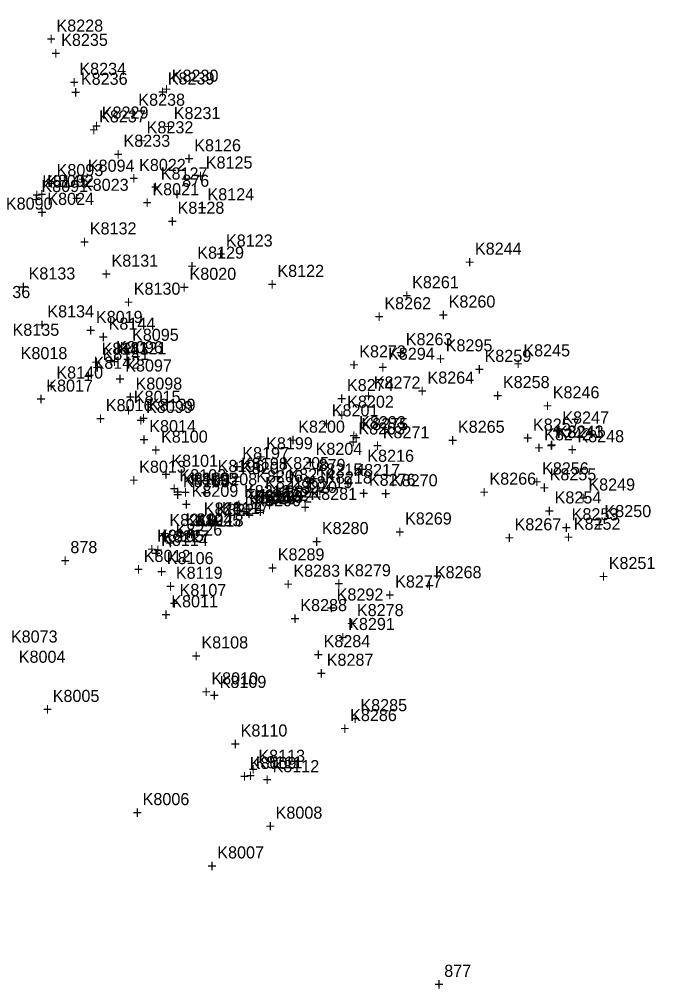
# Model space of a CAD drawing. Extents: x 1036751 to 1042192, y 772604 to 785439.
# Drawn here: x 1041667.1 to 1041798.6, y 774531.3 to 774731.8 of the extents above; entities that cross this region are included whole.
import ezdxf

# ---------------------------------------------------------------- set-up
doc = ezdxf.new("R2010")
doc.units = 0
for name, color, linetype in [('S_Buildings', 7, 'Continuous'), ('S_Buildings_SillElevation', 7, 'Continuous'), ('S_Control_Temp_Traverse', 7, 'Continuous'), ('S_Drainage_Culvert_Top', 7, 'Continuous'), ('S_Drainage_Invert', 7, 'Continuous'), ('S_Drainage_Waterway', 7, 'Continuous'), ('S_Ground_Elevation', 7, 'Continuous'), ('S_Ground_LevelString', 7, 'Continuous'), ('S_Ground_SpotElevation', 7, 'Continuous'), ('S_Roadway_Drive_Gravel', 7, 'Continuous'), ('S_Traffic_Post_Conc', 7, 'Continuous'), ('S_Trees_Decid_NonPay', 7, 'Continuous'), ('S_Trees_Decid_Pay', 7, 'Continuous'), ('S_Trees_TreeLine', 7, 'Continuous'), ('S_Utilities_GuyWire3', 7, 'Continuous'), ('S_Utilities_Pole_Power', 7, 'Continuous')]:
    doc.layers.add(name, color=color, linetype=linetype)

msp = doc.modelspace()

# ---------------------------------------------------------------- texts
at = {"layer": 'S_Buildings'}
for s, p in [('K8228', (1041674.79, 774729.22)), ('+', (1041672.73, 774726.47)), ('K8230', (1041698.64, 774718.86)), ('+', (1041696.57, 774716.11)), ('K8229', (1041684.16, 774711.23)), ('+', (1041682.1, 774708.48)), ('K8145', (1041671.84, 774696.97)), ('+', (1041669.77, 774694.22)), ('K8122', (1041720.5, 774678.48)), ('+', (1041718.44, 774675.73)), ('K8121', (1041687.87, 774662.5)), ('+', (1041685.81, 774659.75)), ('K8120', (1041700.97, 774635.52)), ('+', (1041698.91, 774632.77)), ('K8115', (1041714.71, 774631.45)), ('+', (1041712.65, 774628.7)), ('K8114', (1041696.46, 774622.84)), ('+', (1041694.4, 774620.09)), ('K8113', (1041716.57, 774578.16)), ('+', (1041714.51, 774575.41))]:
    msp.add_text(s, height=2.5, dxfattribs=at).set_placement(p)
at = {"layer": 'S_Buildings_SillElevation'}
for s, p in [('K8234', (1041679.53, 774720.28)), ('+', (1041677.47, 774717.53)), ('K8139', (1041693.9, 774650.78)), ('+', (1041691.84, 774648.03)), ('K8119', (1041699.5, 774616.03)), ('+', (1041697.43, 774613.28))]:
    msp.add_text(s, height=2.5, dxfattribs=at).set_placement(p)
at = {"layer": 'S_Control_Temp_Traverse'}
for s, p in [('876', (1041700.82, 774697.14)), ('876', (1041700.82, 774697.14)), ('+', (1041698.76, 774694.39)), ('+', (1041698.76, 774694.39)), ('879', (1041729.04, 774638.33)), ('+', (1041726.98, 774635.58)), ('878', (1041677.67, 774621.34)), ('878', (1041677.67, 774621.34)), ('878', (1041677.67, 774621.34)), ('+', (1041675.61, 774618.59)), ('+', (1041675.61, 774618.59)), ('+', (1041675.61, 774618.59)), ('877', (1041755.03, 774533.69)), ('877', (1041755.03, 774533.69)), ('877', (1041755.03, 774533.69)), ('877', (1041755.03, 774533.69)), ('+', (1041752.97, 774530.94)), ('+', (1041752.97, 774530.94)), ('+', (1041752.97, 774530.94)), ('+', (1041752.97, 774530.94))]:
    msp.add_text(s, height=2.5, dxfattribs=at).set_placement(p)
at = {"layer": 'S_Drainage_Culvert_Top'}
for s, p in [('K8242', (1041775.71, 774644.67)), ('K8241', (1041778.24, 774645.13)), ('+', (1041773.65, 774641.92)), ('+', (1041776.18, 774642.38))]:
    msp.add_text(s, height=2.5, dxfattribs=at).set_placement(p)
at = {"layer": 'S_Drainage_Invert'}
for s, p in [('K8243', (1041778.35, 774645.24)), ('+', (1041776.29, 774642.49))]:
    msp.add_text(s, height=2.5, dxfattribs=at).set_placement(p)
at = {"layer": 'S_Drainage_Waterway'}
for s, p in [('K8244', (1041761.38, 774683.08)), ('+', (1041759.32, 774680.33)), ('K8245', (1041771.4, 774662.04)), ('+', (1041769.34, 774659.29)), ('K8246', (1041777.48, 774653.36)), ('+', (1041775.42, 774650.61)), ('K8247', (1041779.46, 774648.15)), ('+', (1041777.4, 774645.4)), ('K8248', (1041782.58, 774644.29)), ('+', (1041780.52, 774641.54)), ('K8249', (1041784.85, 774634.29)), ('+', (1041782.79, 774631.54)), ('K8250', (1041788.19, 774628.79)), ('+', (1041786.12, 774626.04))]:
    msp.add_text(s, height=2.5, dxfattribs=at).set_placement(p)
at = {"layer": 'S_Ground_Elevation'}
for s, p in [('K8235', (1041675.76, 774726.27)), ('+', (1041673.69, 774723.52)), ('K8236', (1041679.85, 774718.22)), ('K8239', (1041697.83, 774718.28)), ('+', (1041677.79, 774715.47)), ('K8238', (1041691.73, 774713.89)), ('+', (1041695.77, 774715.53)), ('K8237', (1041683.62, 774710.44)), ('+', (1041689.67, 774711.14)), ('K8231', (1041699.05, 774711.13)), ('K8232', (1041693.45, 774708.18)), ('+', (1041696.99, 774708.38)), ('+', (1041681.56, 774707.69)), ('K8233', (1041688.66, 774705.4)), ('+', (1041691.39, 774705.43)), ('K8126', (1041703.3, 774704.46)), ('+', (1041686.6, 774702.65)), ('K8094', (1041681.28, 774700.24)), ('+', (1041701.24, 774701.71)), ('K8125', (1041705.69, 774700.9)), ('K8093', (1041674.82, 774699.34)), ('K8127', (1041696.38, 774698.63)), ('+', (1041703.63, 774698.15)), ('K8091', (1041671.68, 774696.04)), ('+', (1041672.76, 774696.59)), ('K8092', (1041672.86, 774697.09)), ('+', (1041679.21, 774697.49)), ('+', (1041670.8, 774694.34)), ('+', (1041694.32, 774695.88)), ('K8124', (1041706.04, 774694.33)), ('K8090', (1041664.32, 774692.4)), ('+', (1041669.62, 774693.29)), ('K8128', (1041699.86, 774691.54)), ('+', (1041703.98, 774691.58)), ('+', (1041697.8, 774688.79)), ('K8132', (1041681.69, 774687.27)), ('+', (1041679.63, 774684.52)), ('K8123', (1041709.86, 774684.76)), ('K8129', (1041703.93, 774682.25)), ('+', (1041707.8, 774682.01)), ('K8131', (1041686.18, 774680.6)), ('K8133', (1041669.02, 774677.95)), ('+', (1041701.87, 774679.5)), ('+', (1041684.12, 774677.85)), ('K8261', (1041748.38, 774676.14)), ('K8136', (1041659.7, 774674.11)), ('+', (1041666.96, 774675.2)), ('K8130', (1041690.78, 774674.8)), ('+', (1041688.72, 774672.05)), ('K8262', (1041742.64, 774671.79)), ('+', (1041746.32, 774673.39)), ('K8260', (1041755.94, 774672.14)), ('K8134', (1041672.9, 774670.11)), ('+', (1041740.58, 774669.04)), ('+', (1041753.88, 774669.39)), ('K8135', (1041665.7, 774666.3)), ('+', (1041670.84, 774667.36)), ('K8095', (1041690.43, 774665.26)), ('K8263', (1041747.07, 774664.35)), ('K8096', (1041687.13, 774662.69)), ('+', (1041688.37, 774662.51)), ('K8273', (1041737.44, 774661.83)), ('+', (1041745.01, 774661.6)), ('K8259', (1041763.37, 774660.91)), ('+', (1041685.07, 774659.94)), ('K8097', (1041689.02, 774658.9)), ('+', (1041735.38, 774659.08)), ('+', (1041761.31, 774658.16)), ('+', (1041686.96, 774656.15)), ('K8264', (1041751.56, 774656.41)), ('K8098', (1041691.15, 774655.16)), ('K8274', (1041734.9, 774654.86)), ('K8272', (1041740.44, 774655.39)), ('K8258', (1041767.17, 774655.48)), ('+', (1041689.09, 774652.41)), ('+', (1041732.84, 774652.11)), ('+', (1041738.38, 774652.64)), ('+', (1041749.5, 774653.66)), ('+', (1041765.11, 774652.73)), ('K8099', (1041693.34, 774650.33)), ('K8201', (1041731.76, 774649.63)), ('K8202', (1041734.94, 774651.42)), ('+', (1041732.88, 774648.67)), ('+', (1041691.28, 774647.58)), ('K8200', (1041724.81, 774646.26)), ('+', (1041729.7, 774646.88)), ('K8203', (1041737.27, 774645.89)), ('K8275', (1041737.89, 774646.78)), ('K8265', (1041757.86, 774646.24)), ('K8257', (1041773.39, 774646.68)), ('K8100', (1041696.43, 774644.2)), ('+', (1041735.83, 774644.03)), ('K8271', (1041742.3, 774645.1)), ('+', (1041771.33, 774643.93)), ('K8199', (1041718.18, 774642.81)), ('+', (1041722.75, 774643.51)), ('K8204', (1041728.41, 774641.67)), ('+', (1041735.21, 774643.14)), ('+', (1041740.24, 774642.35)), ('+', (1041755.8, 774643.49)), ('+', (1041694.37, 774641.45)), ('K8197', (1041713.24, 774640.78)), ('+', (1041716.12, 774640.06)), ('K8101', (1041698.56, 774639.2)), ('K8196', (1041708.14, 774638.14)), ('+', (1041711.18, 774638.03)), ('K8207', (1041712.99, 774637.71)), ('K8205', (1041721.55, 774638.72)), ('+', (1041726.35, 774638.92)), ('K8256', (1041775.28, 774637.63)), ('+', (1041696.5, 774636.45)), ('K8102', (1041700.23, 774636.21)), ('K8195', (1041702.59, 774635.46)), ('K8206', (1041716.14, 774636)), ('+', (1041719.49, 774635.97)), ('K8214', (1041722.78, 774636.33)), ('K8215', (1041728.41, 774637.41)), ('K8218', (1041730.39, 774635.74)), ('K8217', (1041736.22, 774637.28)), ('K8266', (1041764.38, 774635.5)), ('K8255', (1041776.83, 774636.4)), ('K8103', (1041700.96, 774634.98)), ('+', (1041706.08, 774635.39)), ('K8208', (1041706.66, 774635.38)), ('+', (1041710.93, 774634.96)), ('K8213', (1041717.95, 774634.62)), ('K8220', (1041723.16, 774633.78)), ('+', (1041726.35, 774634.66)), ('K8219', (1041726.4, 774634.75)), ('+', (1041734.16, 774634.53)), ('K8276', (1041739.44, 774635.27)), ('K8270', (1041744, 774635.16)), ('+', (1041773.22, 774634.88)), ('+', (1041698.17, 774633.46)), ('+', (1041698.9, 774632.23)), ('+', (1041700.53, 774632.71)), ('K8209', (1041702.75, 774632.99)), ('+', (1041704.6, 774632.63)), ('K8212', (1041713.6, 774632.92)), ('K8223', (1041713.73, 774631.69)), ('+', (1041714.08, 774633.25)), ('K8116', (1041715.7, 774632)), ('K8222', (1041717.2, 774632.12)), ('K8282', (1041718.03, 774631.76)), ('K8221', (1041719.97, 774632.83)), ('+', (1041720.72, 774633.58)), ('+', (1041724.34, 774632)), ('K8281', (1041727.33, 774632.36)), ('+', (1041728.33, 774632.99)), ('+', (1041737.38, 774632.52)), ('+', (1041741.94, 774632.41)), ('+', (1041762.31, 774632.75)), ('+', (1041774.77, 774633.65)), ('K8254', (1041777.87, 774631.61)), ('+', (1041700.69, 774630.24)), ('K8117', (1041709.03, 774629.45)), ('+', (1041711.54, 774630.17)), ('K8290', (1041715.74, 774631.02)), ('+', (1041715.89, 774631.87)), ('+', (1041717.91, 774630.08)), ('+', (1041721.1, 774631.03)), ('K8211', (1041705.27, 774629.32)), ('K8224', (1041707.9, 774629.05)), ('+', (1041711.67, 774628.94)), ('+', (1041713.64, 774629.25)), ('+', (1041713.67, 774628.27)), ('+', (1041715.14, 774629.37)), ('+', (1041715.97, 774629.01)), ('+', (1041725.27, 774629.61)), ('+', (1041775.81, 774628.86)), ('K8253', (1041781.4, 774628.14)), ('K8104', (1041701.53, 774627.07)), ('+', (1041703.21, 774626.57)), ('K8225', (1041703.38, 774626.9)), ('K8118', (1041703.85, 774626.85)), ('+', (1041705.84, 774626.3)), ('+', (1041706.97, 774626.7)), ('K8269', (1041746.92, 774627.26)), ('K8267', (1041769.58, 774626.05)), ('K8252', (1041781.84, 774626.18)), ('K8105', (1041695.62, 774623.7)), ('K8227', (1041696.84, 774623.55)), ('+', (1041699.47, 774624.32)), ('K8226', (1041699.43, 774624.96)), ('+', (1041701.32, 774624.15)), ('+', (1041701.79, 774624.1)), ('K8280', (1041729.71, 774625.28)), ('+', (1041744.86, 774624.51)), ('+', (1041779.33, 774625.39)), ('+', (1041697.37, 774622.21)), ('+', (1041727.65, 774622.53)), ('+', (1041767.52, 774623.3)), ('+', (1041779.78, 774623.43)), ('+', (1041693.56, 774620.95)), ('+', (1041694.78, 774620.8)), ('K8289', (1041720.58, 774619.83)), ('K8106', (1041697.63, 774619.07)), ('K8251', (1041789.06, 774618.05)), ('+', (1041695.57, 774616.32)), ('+', (1041718.52, 774617.08)), ('K8283', (1041723.81, 774616.46)), ('K8279', (1041734.32, 774616.55)), ('K8268', (1041753.08, 774616.15)), ('K8277', (1041744.87, 774614.23)), ('+', (1041787, 774615.3)), ('K8107', (1041700.27, 774612.48)), ('+', (1041721.75, 774613.71)), ('+', (1041732.26, 774613.8)), ('+', (1041751.02, 774613.4)), ('+', (1041742.81, 774611.48)), ('+', (1041698.21, 774609.73)), ('K8288', (1041725.25, 774609.35)), ('K8278', (1041736.96, 774608.32)), ('+', (1041723.18, 774606.6)), ('+', (1041734.9, 774605.57)), ('K8108', (1041704.78, 774601.63)), ('K8284', (1041730.06, 774601.89)), ('+', (1041702.72, 774598.88)), ('+', (1041728, 774599.14)), ('K8287', (1041730.71, 774598.03)), ('K8109', (1041708.56, 774593.46)), ('+', (1041728.64, 774595.28)), ('+', (1041706.5, 774590.71)), ('K8285', (1041737.68, 774588.65)), ('+', (1041735.62, 774585.9)), ('K8286', (1041735.56, 774586.6)), ('K8110', (1041712.9, 774583.41)), ('+', (1041733.5, 774583.85)), ('+', (1041710.84, 774580.66)), ('K8111', (1041716.02, 774576.84)), ('K8112', (1041719.5, 774576.03)), ('+', (1041713.96, 774574.09)), ('+', (1041717.43, 774573.28))]:
    msp.add_text(s, height=2.5, dxfattribs=at).set_placement(p)
at = {"layer": 'S_Ground_LevelString'}
msp.add_text('K8073', height=2.5, dxfattribs=at).set_placement((1041665.36, 774602.84))
at = {"layer": 'S_Ground_SpotElevation'}
for s, p in [('K8216', (1041739.11, 774640.23)), ('+', (1041737.05, 774637.48)), ('K8210', (1041698.16, 774626.95)), ('+', (1041696.1, 774624.2))]:
    msp.add_text(s, height=2.5, dxfattribs=at).set_placement(p)
at = {"layer": 'S_Roadway_Drive_Gravel'}
for s, p in [('K8022', (1041691.89, 774700.39)), ('K8023', (1041680.06, 774696.29)), ('+', (1041689.83, 774697.64)), ('K8021', (1041694.64, 774695.37)), ('K8024', (1041672.9, 774693.38)), ('+', (1041678, 774693.54)), ('+', (1041692.58, 774692.62)), ('+', (1041670.84, 774690.63)), ('K8020', (1041702.32, 774677.88)), ('+', (1041700.26, 774675.13)), ('K8019', (1041682.96, 774668.95)), ('+', (1041680.89, 774666.2)), ('K8018', (1041667.38, 774661.47)), ('K8017', (1041672.68, 774654.75)), ('+', (1041670.61, 774652)), ('K8015', (1041690.8, 774652.43)), ('K8016', (1041685, 774650.71)), ('+', (1041682.94, 774647.96)), ('+', (1041688.74, 774649.68)), ('K8014', (1041693.99, 774646.37)), ('+', (1041691.93, 774643.62)), ('K8013', (1041691.9, 774637.97)), ('+', (1041689.84, 774635.22)), ('K8012', (1041692.86, 774619.52)), ('+', (1041690.79, 774616.77)), ('K8011', (1041698.55, 774610.13)), ('+', (1041696.49, 774607.38)), ('K8004', (1041666.99, 774598.66)), ('K8010', (1041706.84, 774594.19)), ('K8005', (1041674.01, 774590.56)), ('+', (1041704.78, 774591.44)), ('+', (1041671.95, 774587.81)), ('K8009', (1041714.79, 774576.69)), ('+', (1041712.73, 774573.94)), ('K8006', (1041692.62, 774569.22)), ('+', (1041690.56, 774566.47)), ('K8008', (1041720.14, 774566.41)), ('+', (1041718.08, 774563.66)), ('K8007', (1041708.07, 774558.19)), ('+', (1041706.01, 774555.44))]:
    msp.add_text(s, height=2.5, dxfattribs=at).set_placement(p)
at = {"layer": 'S_Traffic_Post_Conc'}
for s, p in [('K8142', (1041682.46, 774659.47)), ('+', (1041680.4, 774656.72))]:
    msp.add_text(s, height=2.5, dxfattribs=at).set_placement(p)
at = {"layer": 'S_Trees_Decid_NonPay'}
for s, p in [('K8144', (1041685.58, 774667.57)), ('+', (1041683.52, 774664.82)), ('K8143', (1041684.13, 774662.39)), ('+', (1041682.07, 774659.64))]:
    msp.add_text(s, height=2.5, dxfattribs=at).set_placement(p)
at = {"layer": 'S_Trees_Decid_Pay'}
for s, p in [('K8198', (1041713, 774638.61)), ('+', (1041710.94, 774635.86))]:
    msp.add_text(s, height=2.5, dxfattribs=at).set_placement(p)
at = {"layer": 'S_Trees_TreeLine'}
for s, p in [('K8295', (1041755.33, 774663.08)), ('K8294', (1041743.4, 774661.34)), ('+', (1041753.27, 774660.33)), ('+', (1041741.34, 774658.59)), ('K8293', (1041737.42, 774647.18)), ('+', (1041735.36, 774644.43)), ('K8292', (1041732.77, 774611.54)), ('+', (1041730.71, 774608.79)), ('K8291', (1041735.15, 774605.44)), ('+', (1041733.09, 774602.69))]:
    msp.add_text(s, height=2.5, dxfattribs=at).set_placement(p)
at = {"layer": 'S_Utilities_GuyWire3'}
for s, p in [('K8141', (1041684.33, 774661.29)), ('+', (1041682.27, 774658.54))]:
    msp.add_text(s, height=2.5, dxfattribs=at).set_placement(p)
at = {"layer": 'S_Utilities_Pole_Power'}
for s, p in [('K8140', (1041674.77, 774657.46)), ('+', (1041672.71, 774654.71))]:
    msp.add_text(s, height=2.5, dxfattribs=at).set_placement(p)

doc.saveas('drawing.dxf')
